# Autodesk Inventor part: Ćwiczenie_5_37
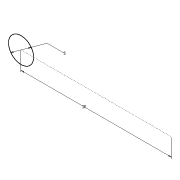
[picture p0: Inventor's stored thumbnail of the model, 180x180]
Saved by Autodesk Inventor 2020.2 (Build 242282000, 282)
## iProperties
Created: 2005-04
Part Number: Ćwiczenie_5_37
Document SubType Name: Modeling
Designer: F.Stasiak
Manufacturer: Standard
Standards Organization: Custom
Density: 1 g/cm^3
Material: Ogólny
Appearance: Domyślna
Manager: www.cadconsulting.pl
Company: Fabian Stasiak CAD Consulting
Author: F.Stasiak
Subject: Zbiór ćwiczeń. Autodesk Inventor 2020. Kurs podstawowy
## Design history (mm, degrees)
sketch "Szkic2"
  geometry: L1 (0, 0)-(30, 0); C1 r 2.5 at (30, 0)
  constraints: 2 end point, 1 centre point, 1 horizontal
  dimensions: "d0" = 30 dimension on L1.start C1 L1.end L1; "d0" = 30 distance of L1.start L1.end; "d1" = 5 diameter of C1
node "Korpusy bryłowe"
node "Korpusy powierzchniowe"
